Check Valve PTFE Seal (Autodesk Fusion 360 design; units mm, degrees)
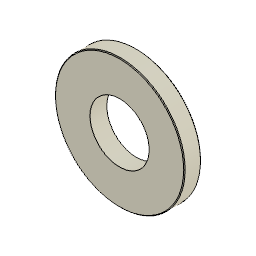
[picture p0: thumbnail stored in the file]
description: Part Number
part number: 96371A203_Abrasion-Resistant ePTFE Plastic Sealing Washer
sketch "Sketch1" plane through (0, 0, 0) normal (0, 0, 1) x axis (1, 0, 0)
  line L1 (0, -2.7861) -> (0, 6.6013)
  line L2 (-6.9596, 0) -> (-4.064, 0)
  line L3 (-6.9596, 1.8136) -> (-6.9596, 0)
  line L4 (-3.175, 1.8136) -> (-6.9596, 1.8136)
  line L5 (-3.175, 0.889) -> (-3.175, 1.8136)
  line L6 (-4.064, 0) -> (-3.175, 0.889)
  line L7 (-3.175, 0) -> (-3.175, 0.889)
  line L8 (-4.064, 0) -> (-3.175, 0)
  point P1 (0, 0)
  vertical L1
  coincident P1 L1
  horizontal L2
  perpendicular L2 L3
  perpendicular L3 L4
  perpendicular L4 L5
  coincident P1 L2
  perpendicular L4 L7
  perpendicular L7 L8
  dimension "d1" angle L4 L6 = 45
  dimension "d2" distance L2 L4 = 1.8136
  dimension "d5" = 8.128
  dimension "d6" = 6.35
  dimension "d7" = 13.9192
revolve "Revolve2" sketch "Sketch1" AlongAngle 360
chamfer "Chamfer2" distance 0.0762
chamfer "Chamfer3" distance 0.0762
